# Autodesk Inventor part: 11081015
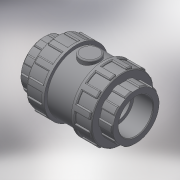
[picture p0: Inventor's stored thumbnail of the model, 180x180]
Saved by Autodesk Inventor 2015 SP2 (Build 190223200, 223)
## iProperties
Created: 2017-11
Part Number: 11081015
Material: Generic
Description: PLASSON CHECK VALVE THR 1 1/2" PTFE COATED SPRING + EPDM O-RING
Document SubType Name: Modeling
Designer: KIM
Density: 1 g/cm^3
Appearance: Default
Author: KIM
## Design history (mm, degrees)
derived "110810 - 110610 110910 - 110010.ipt"
feature "Solid1::110810 - 110610 110910 - 110010.ipt"
tag "TaggingFeature1"
body "Solid1"
other parameters: "d0" = 142, "d1" = 44.845, "d2" = 96, "d3" = 31, "d4" = 35.876, "d5" = 21.7, "d7" = 62.783, "d8" = 86.4, "d13" = 1.34535, "d23" = 31, "d24" = 92.16, "d25" = 0.8969, "d26" = 1.34535, "d27" = 14.4, "d28" = 7.2, "d29" = 23.25, "d30" = 0, "d35" = 1.34535, "d39" = 48, "d45" = 360 deg, "d47" = 0.8969, "d50" = 48, "d51" = 28.8, "d53" = 0, "d54" = 1.92, "d55" = 8.969, "d56" = 4.4845, "d58" = 0, "d59" = 1.34535, "d61" = 360 deg, "G_" = 44.845, "l_" = 31, "H_" = 142, "K_" = 96
